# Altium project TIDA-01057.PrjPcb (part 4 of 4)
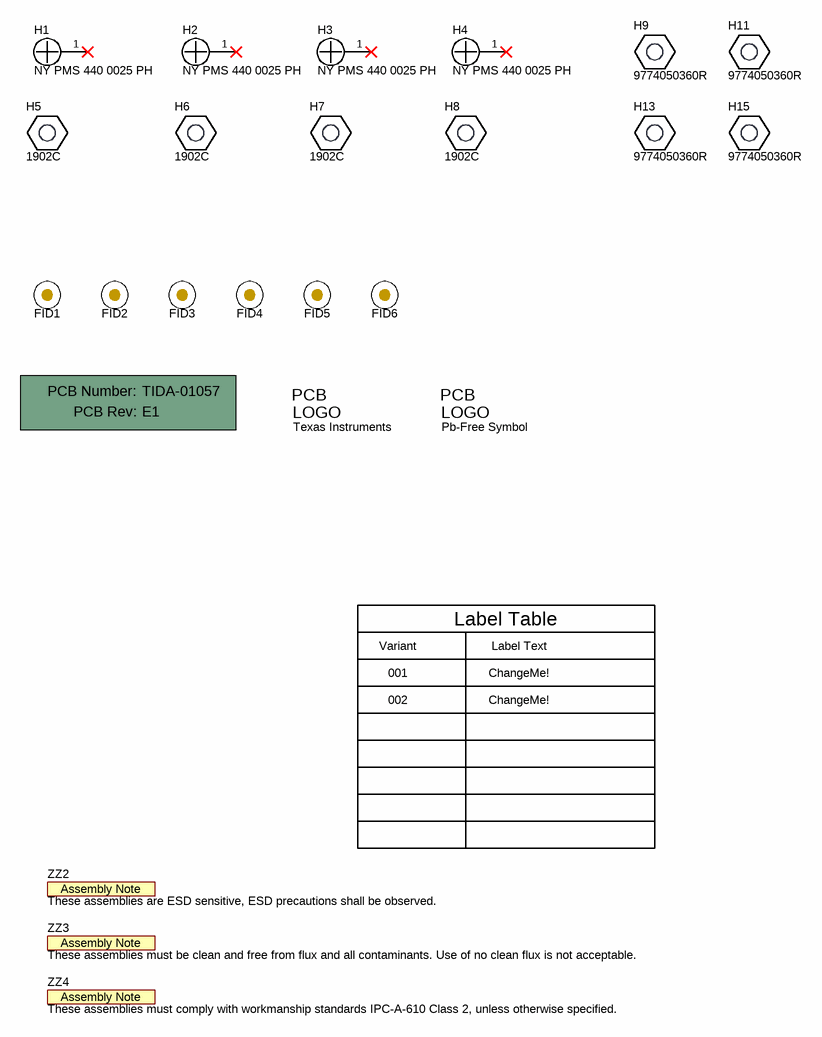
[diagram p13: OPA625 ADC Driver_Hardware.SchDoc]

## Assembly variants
001: not fitted C83 C89 C90 C104 C105 C106 C107 C108 C109 C110 C111 C112 C113 C114 C115 C116 C117 C118 C119 C120 C121 C122 C304 C305 C306 C307 C308 C316 C317 C323 C335 C343 C344 C345 C346 C409 CMFB FID1 FID2 FID3 FID4 FID5 FID6 OPAN_2 OPAP_2 R11 R12 R15 R17 R18 R20 R25 R26 R27 R29 R30 R31 R33 R34 R90 R99 R110 R112 R113 R114 R115 R116 R117 R213 R223 R225 R226 R240 R250 R252 R255 R260 R261 R262 R263 R269 R288 R453 R457 RDN3 RDN4 RDP3 RDP4 REN0 REN1 RMFBN RMFBP RR457 U1 U2 U31 U32 UADS2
